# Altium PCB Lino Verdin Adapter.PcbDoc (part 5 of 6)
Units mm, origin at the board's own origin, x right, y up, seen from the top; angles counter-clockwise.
Board outline 69.6 x 35 mm, 8 copper layers (Top Layer, Mid 1, GND 1, Mid 2, Mid 3, GND 2, Mid 4, Bottom Layer), stack 1.198 mm thick; 208 components, 258 nets, 1063 pads, 1090 vias.
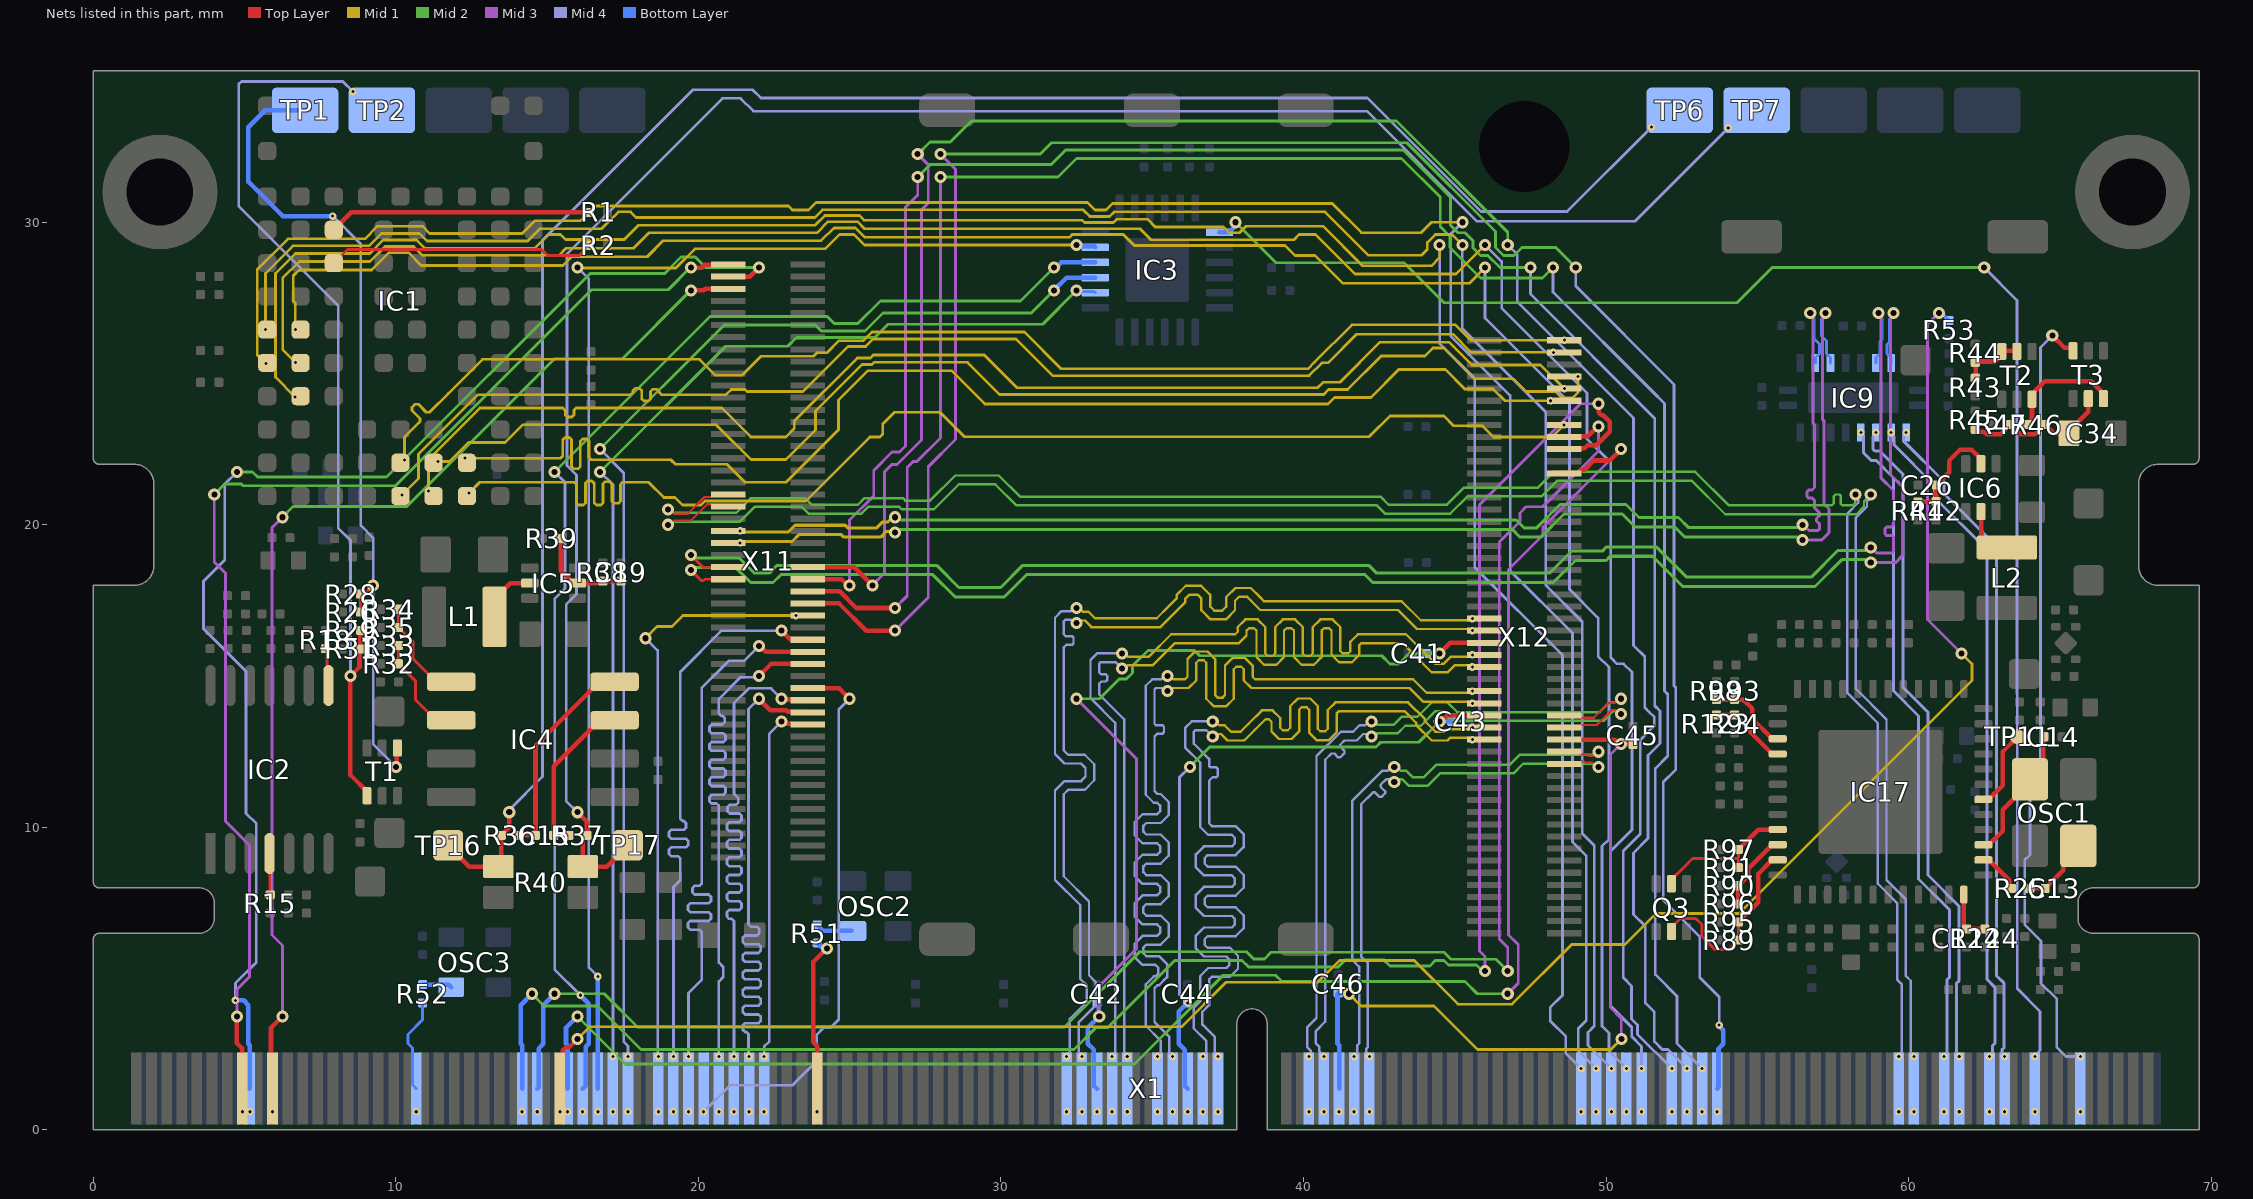
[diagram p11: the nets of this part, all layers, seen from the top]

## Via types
v1: diameter 0.4, hole 0.2, Top Layer to Bottom Layer, tented both sides, 600 vias
v2: diameter 0.25, hole 0.1, Mid 4 to Bottom Layer, tented both sides, 229 vias
v3: diameter 0.25, hole 0.1, Top Layer to Mid 1, tented both sides, 216 vias
v4: diameter 0.25, hole 0.1, Top Layer to Mid 1, tented top, 41 vias
v5: diameter 0.4, hole 0.2, Top Layer to Bottom Layer, 4 vias

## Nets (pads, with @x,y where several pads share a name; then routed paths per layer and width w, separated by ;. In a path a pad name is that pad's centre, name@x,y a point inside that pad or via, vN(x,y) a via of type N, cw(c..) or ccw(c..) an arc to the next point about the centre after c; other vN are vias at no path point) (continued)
MSP_16/17_N: X1.124 X12.S47 | length 32.8
  Mid 4 w0.08: v2(32.175,2.425) 32.175,2.452 32.28,2.557 32.28,3.671 32.84,4.231 32.84,4.769 32.62,4.989 32.62,7.43 31.787,8.263 31.787,9.34 31.787,11.215 32.102,11.53 32.651,11.53 32.796,11.675 32.796,11.965 32.651,12.11 32.102,12.11 31.787,12.425 31.787,12.67 31.787,16.928 32.004,17.145 32.308,17.145 32.413,17.25 v1(32.5,17.25)
  Mid 1 w0.08: v1(32.5,17.25) 32.587,17.25 32.711,17.126 32.893,17.126 33.109,16.91 35.15,16.91 35.55,17.31 35.807,17.568 35.807,17.682 36.11,17.984 36.615,17.984 36.917,17.682 36.917,17.298 37.05,17.165 37.315,17.165 37.447,17.298 37.447,17.607 37.75,17.91 38.255,17.91 38.557,17.607 38.69,17.475 40.195,17.475 43.245,17.475 43.875,16.845 45.479,16.845 45.534,16.9 v3(45.58,16.9)
  other v2: 32.175,0.6
MSP_16/17_P: X1.126 X12.S49 | length 32.8
  Mid 4 w0.08: v1(32.5,16.75) 32.413,16.75 32.308,16.855 32.124,16.855 32.077,16.808 32.077,16.383 32.14,16.32 32.353,16.32 32.4,16.273 32.4,16.077 32.353,16.03 32.157,16.03 32.077,15.95 32.077,12.67 32.077,12.545 32.222,12.4 32.771,12.4 33.086,12.085 33.086,11.555 32.771,11.24 32.222,11.24 32.077,11.095 32.077,9.34 32.077,8.383 32.91,7.55 32.91,5.109 33.13,4.889 33.13,4.111 32.57,3.551 32.57,2.557 32.675,2.452 v2(32.675,2.425)
  Mid 1 w0.08: v1(32.5,16.75) 32.587,16.75 32.673,16.836 32.773,16.836 32.989,16.62 35.27,16.62 35.55,16.9 36.097,17.447 36.097,17.562 36.23,17.694 36.495,17.694 36.627,17.562 36.627,17.178 36.93,16.875 37.435,16.875 37.737,17.178 37.737,17.487 37.87,17.62 38.135,17.62 38.267,17.487 38.57,17.185 40.195,17.185 40.44,17.185 43.125,17.185 43.755,16.555 45.479,16.555 45.534,16.5 v3(45.58,16.5)
  other v2: 32.675,0.6
MSP_18: C41.2 C42.2 X1.128 X12.S51 | length 30.2
  Top Layer w0.15: v1(44.5,15.75) 44.85,16.1 X12.S51@45.98,16.1
  Mid 3 w0.095: v1(32.5,14.25) 34.48,12.27 34.48,5.989 33.25,4.759 v1(33.25,3.75)
  Mid 2 w0.095: v1(32.5,14.25) 33.259,14.25 33.911,14.902 34.144,14.902 34.348,15.106 34.348,15.339 34.859,15.85 36.39,15.85 36.57,15.67 42.589,15.67 42.856,15.403 43.144,15.403 43.491,15.75 v1(44.5,15.75)
  Bottom Layer w0.15: C42.2@33.17,4.2 33.236,4.134 33.236,3.764 v1(33.25,3.75) 32.875,3.375 32.875,2.845 33.075,2.645 33.075,1.462 X1.128@33.175,1.362 ; C41.2@44.06,15.75 v1(44.5,15.75)
  other v2: 33.175,0.6
MSP_19/20_N: X1.130 X12.S53 | length 32.8
  Mid 4 w0.08: v2(33.675,2.425) 33.675,2.452 33.78,2.557 33.78,4.062 33.78,13.451 32.96,14.271 32.96,15.533 33.177,15.75 v1(34,15.75)
  Mid 1 w0.08: v1(34,15.75) 34.087,15.75 34.192,15.645 34.895,15.645 35.63,16.38 37.745,16.38 37.827,16.462 37.827,16.62 38.08,16.873 38.485,16.873 38.737,16.62 38.737,15.745 38.82,15.663 38.985,15.663 39.067,15.745 39.067,16.62 39.32,16.873 39.725,16.873 39.977,16.62 39.977,15.745 40.06,15.663 40.225,15.663 40.307,15.745 40.307,16.62 40.56,16.873 40.965,16.873 41.217,16.62 41.217,15.831 41.3,15.749 41.479,15.749 41.547,15.817 41.547,16.128 41.8,16.38 43.389,16.38 44.359,15.41 44.641,15.41 44.876,15.645 45.479,15.645 45.534,15.7 v3(45.58,15.7)
  other v2: 33.675,0.6
MSP_19/20_P: X1.132 X12.S55 | length 32.8
  Mid 4 w0.08: v1(34,15.25) 33.79,15.46 33.297,15.46 33.25,15.413 33.25,15.12 33.31,15.06 33.463,15.06 33.51,15.013 33.51,14.867 33.463,14.82 33.32,14.82 33.25,14.75 33.25,14.391 34.07,13.571 34.07,3.942 34.07,2.557 34.175,2.452 v2(34.175,2.425)
  Mid 1 w0.08: v1(34,15.25) 34.087,15.25 34.192,15.355 35.015,15.355 35.75,16.09 37.62,16.09 37.865,16.09 38.117,16.342 38.117,16.5 38.2,16.583 38.365,16.583 38.447,16.5 38.447,15.625 38.7,15.373 39.105,15.373 39.357,15.625 39.357,16.5 39.44,16.583 39.605,16.583 39.687,16.5 39.687,15.625 39.94,15.373 40.345,15.373 40.597,15.625 40.597,16.5 40.68,16.583 40.845,16.583 40.927,16.5 40.927,15.711 41.18,15.459 41.599,15.459 41.837,15.697 41.837,16.008 41.92,16.09 42.729,16.09 43.269,16.09 44.239,15.12 44.761,15.12 44.996,15.355 45.479,15.355 45.534,15.3 v3(45.58,15.3)
  other v2: 34.175,0.6
MSP_21/22_N: X1.136 X12.S59 | length 32.8
  Mid 4 w0.08: v2(35.175,2.425) 35.175,2.452 35.28,2.557 35.28,2.951 34.787,3.444 34.787,4.15 34.787,4.808 35.052,5.073 35.11,5.073 35.205,5.168 35.205,5.358 35.11,5.453 34.683,5.453 34.418,5.718 34.418,6.148 34.683,6.413 35.164,6.413 35.259,6.508 35.259,6.698 35.164,6.793 34.683,6.793 34.418,7.058 34.418,7.488 34.683,7.753 35.164,7.753 35.259,7.848 35.259,8.038 35.164,8.133 34.683,8.133 34.418,8.398 34.418,8.828 34.683,9.093 35.164,9.093 35.259,9.188 35.259,9.378 35.164,9.473 34.683,9.473 34.418,9.738 34.418,10.168 34.683,10.433 35.164,10.433 35.259,10.528 35.259,10.718 35.164,10.813 35.052,10.813 34.787,11.078 34.787,11.323 34.787,14.678 35.004,14.895 35.308,14.895 35.413,15 v1(35.5,15)
  Mid 1 w0.08: v1(35.5,15) 35.587,15 35.692,14.895 36.085,14.895 36.167,14.977 36.167,15.559 36.42,15.812 36.825,15.812 37.077,15.559 37.077,14.368 37.16,14.286 37.325,14.286 37.407,14.368 37.407,15.345 37.66,15.597 38.065,15.597 38.317,15.345 38.317,14.977 38.4,14.895 43.624,14.895 44.074,14.445 45.479,14.445 45.534,14.5 v3(45.58,14.5)
  other v2: 35.175,0.6
MSP_21/22_P: X1.138 X12.S61 | length 32.8
  Mid 4 w0.08: v1(35.5,14.5) 35.413,14.5 35.308,14.605 35.124,14.605 35.077,14.558 35.077,13.423 35.13,13.37 35.343,13.37 35.39,13.323 35.39,13.147 35.343,13.1 35.18,13.1 35.077,12.997 35.077,11.323 35.077,11.198 35.172,11.103 35.284,11.103 35.549,10.838 35.549,10.408 35.284,10.143 34.803,10.143 34.708,10.048 34.708,9.858 34.803,9.763 35.284,9.763 35.549,9.498 35.549,9.068 35.284,8.803 34.803,8.803 34.708,8.708 34.708,8.518 34.803,8.423 35.284,8.423 35.549,8.158 35.549,7.728 35.284,7.463 34.803,7.463 34.708,7.368 34.708,7.178 34.803,7.083 35.284,7.083 35.549,6.818 35.549,6.388 35.284,6.123 34.803,6.123 34.708,6.028 34.708,5.838 34.803,5.743 35.23,5.743 35.495,5.478 35.495,5.048 35.23,4.783 35.172,4.783 35.077,4.688 35.077,4.15 35.077,3.564 35.57,3.071 35.57,2.557 35.675,2.452 v2(35.675,2.425)
  Mid 1 w0.08: v1(35.5,14.5) 35.587,14.5 35.692,14.605 35.96,14.605 36.205,14.605 36.457,14.857 36.457,15.439 36.54,15.522 36.705,15.522 36.787,15.439 36.787,14.248 37.04,13.996 37.445,13.996 37.697,14.248 37.697,15.225 37.78,15.307 37.945,15.307 38.027,15.225 38.027,14.857 38.28,14.605 38.82,14.605 43.504,14.605 43.954,14.155 45.479,14.155 45.534,14.1 v3(45.58,14.1)
  other v2: 35.675,0.6
MSP_23: C43.2 C44.2 X1.140 X12.S63 | length 22
  Top Layer w0.15: v1(44.5,13.5) 44.568,13.5 44.768,13.7 X12.S63@45.98,13.7
  Mid 2 w0.095: v1(36.25,12) 36.902,12.652 42.394,12.652 42.554,12.812 43.812,12.812 v1(44.5,13.5)
  Mid 4 w0.09: v2(36.17,4.2) 35.905,4.465 35.905,11.655 v1(36.25,12)
  Bottom Layer w0.15: v2(36.17,4.2) 35.883,3.913 35.883,3.603 35.875,3.595 35.875,2.845 36.075,2.645 36.075,1.462 X1.140@36.175,1.362 ; v1(44.5,13.5) C43.2@44.9,13.5
  other v2: 36.175,0.6
MSP_24/25_N: X1.142 X12.S65 | length 32.8
  Mid 4 w0.08: v2(36.675,2.425) 36.675,2.452 36.78,2.557 36.78,2.951 36.37,3.361 36.37,4.025 36.59,4.245 36.59,4.67 36.59,4.72 36.59,4.84 36.59,5.085 36.855,5.35 37.451,5.35 37.546,5.445 37.546,5.635 37.451,5.73 36.71,5.73 36.445,5.995 36.445,6.425 36.71,6.69 37.635,6.69 37.73,6.785 37.73,6.975 37.635,7.07 36.71,7.07 36.445,7.335 36.445,7.765 36.71,8.03 37.635,8.03 37.73,8.125 37.73,8.315 37.635,8.41 36.71,8.41 36.445,8.675 36.445,9.105 36.71,9.37 37.635,9.37 37.73,9.465 37.73,9.655 37.635,9.75 36.855,9.75 36.59,10.015 36.59,10.26 36.59,12.141 36.09,12.641 36.09,13.283 36.307,13.5 v1(37,13.5)
  Mid 1 w0.08: v1(37,13.5) 37.087,13.5 37.211,13.376 37.393,13.376 37.609,13.16 37.92,13.16 38.15,13.39 38.19,13.43 38.625,13.865 38.982,13.865 39.234,13.612 39.234,13.292 39.316,13.21 39.481,13.21 39.564,13.292 39.564,14.005 39.816,14.258 40.222,14.258 40.474,14.005 40.474,13.257 40.556,13.175 40.721,13.175 40.804,13.257 40.804,13.878 41.056,14.13 41.301,14.13 43.46,14.13 44.012,13.578 44.012,13.507 44.359,13.16 44.641,13.16 44.726,13.245 45.479,13.245 45.534,13.3 v3(45.58,13.3)
  other v2: 36.675,0.6
MSP_24/25_P: X1.144 X12.S67 | length 32.8
  Mid 4 w0.08: v1(37,13) 36.79,13.21 36.427,13.21 36.38,13.163 36.38,12.761 36.88,12.261 36.88,12.03 36.93,11.98 37.123,11.98 37.17,11.933 37.17,11.707 37.123,11.66 37,11.66 36.88,11.54 36.88,10.26 36.88,10.135 36.975,10.04 37.755,10.04 38.02,9.775 38.02,9.345 37.755,9.08 36.83,9.08 36.735,8.985 36.735,8.795 36.83,8.7 37.755,8.7 38.02,8.435 38.02,8.005 37.755,7.74 36.83,7.74 36.735,7.645 36.735,7.455 36.83,7.36 37.755,7.36 38.02,7.095 38.02,6.665 37.755,6.4 36.83,6.4 36.735,6.305 36.735,6.115 36.83,6.02 37.571,6.02 37.836,5.755 37.836,5.325 37.571,5.06 36.975,5.06 36.88,4.965 36.88,4.84 36.88,4.125 36.66,3.905 36.66,3.481 37.07,3.071 37.07,2.557 37.175,2.452 v2(37.175,2.425)
  Mid 1 w0.08: v1(37,13) 37.087,13 37.173,13.086 37.273,13.086 37.489,12.87 38.04,12.87 38.15,12.98 38.395,13.225 38.745,13.575 38.861,13.575 38.944,13.492 38.944,13.172 39.196,12.92 39.602,12.92 39.854,13.172 39.854,13.885 39.936,13.968 40.101,13.968 40.184,13.885 40.184,13.137 40.436,12.885 40.842,12.885 41.094,13.137 41.094,13.758 41.176,13.84 43.34,13.84 43.722,13.458 43.722,13.387 44.239,12.87 44.761,12.87 44.846,12.955 45.479,12.955 45.534,12.9 v3(45.58,12.9)
  other v2: 37.175,0.6
MSP_26/27_N: X1.148 X12.S64 | length 23.5
  Top Layer w0.075: X12.S64@48.62,13.7 49.09,13.7 49.171,13.619 49.596,13.619 50.096,14.118 50.294,14.118 50.425,14.25 v1(50.5,14.25)
  Mid 2 w0.08: v1(42.25,13.5) 42.337,13.5 42.442,13.395 42.987,13.395 43.242,13.65 43.759,13.65 44.239,14.13 44.761,14.13 45.081,13.81 49.791,13.81 50.107,14.126 50.289,14.126 50.413,14.25 v1(50.5,14.25)
  Mid 4 w0.08: v2(40.175,2.425) 40.175,2.471 40.236,2.532 40.236,2.623 40.12,2.739 40.12,3.389 40.43,3.699 40.43,12.353 41.237,13.16 41.641,13.16 41.857,13.376 42.039,13.376 42.163,13.5 v1(42.25,13.5)
  other v2: 40.175,0.6
MSP_26/27_P: X1.150 X12.S66 | length 23.5
  Top Layer w0.075: X12.S66@48.62,13.3 49.09,13.3 49.171,13.381 49.694,13.381 50.194,13.881 50.294,13.881 50.425,13.75 v1(50.5,13.75)
  Mid 2 w0.08: v1(42.25,13) 42.337,13 42.442,13.105 43.108,13.105 43.363,13.36 43.879,13.36 44.359,13.84 44.641,13.84 44.961,13.52 49.911,13.52 50.227,13.836 50.327,13.836 50.413,13.75 v1(50.5,13.75)
  Mid 4 w0.08: v2(40.675,2.425) 40.675,2.452 40.526,2.601 40.526,2.743 40.41,2.859 40.41,3.269 40.72,3.579 40.72,12.233 40.927,12.44 41.02,12.44 41.147,12.313 41.213,12.313 41.357,12.457 41.357,12.523 41.217,12.663 41.217,12.73 41.357,12.87 41.761,12.87 41.977,13.086 42.077,13.086 42.163,13 v1(42.25,13)
  other v2: 40.675,0.6
MSP_28: C45.2 C46.2 X1.152 X12.S68 | length 25.8
  Top Layer w0.15: X12.S68@48.62,12.9 50.282,12.9 50.432,12.75 v1(50.5,12.75) 50.505,12.745 50.885,12.745 C45.2@50.89,12.74
  Mid 3 w0.095: v1(50.5,12.75) 50.153,12.402 50.153,4.042 50.505,3.689 v1(50.505,3.005)
  Mid 1 w0.09: v1(41.5,4.5) 41.905,4.095 44.315,4.095 45.755,2.655 50.155,2.655 v1(50.505,3.005)
  Bottom Layer w0.15: X1.152@41.175,1.362 41.175,2.795 41.125,2.845 41.125,3.155 41.125,4.505 C46.2@41.15,4.53 41.165,4.515 41.485,4.515 v1(41.5,4.5)
  other v2: 41.175,0.6
MSP_29/30_N: X1.154 X12.S70 | length 18.9
  Top Layer w0.075: X12.S70@48.62,12.5 49.09,12.5 49.174,12.416 49.357,12.416 49.404,12.369 49.544,12.369 49.675,12.5 v1(49.75,12.5)
  Mid 2 w0.08: v1(43,12) 43.087,12 43.211,11.876 43.393,11.876 43.609,11.66 43.98,11.66 44.395,12.075 46.825,12.075 47.145,12.395 49.558,12.395 49.663,12.5 v1(49.75,12.5)
  Mid 4 w0.08: v2(41.675,2.425) 41.675,2.452 41.78,2.557 41.78,2.799 41.84,2.859 41.84,5.391 41.615,5.616 41.615,10.884 42.607,11.876 42.789,11.876 42.913,12 v1(43,12)
  other v2: 41.675,0.6
MSP_29/30_P: X1.156 X12.S72 | length 18.9
  Top Layer w0.075: X12.S72@48.62,12.1 48.682,12.163 49.18,12.163 49.196,12.179 49.259,12.179 49.306,12.132 49.544,12.132 49.675,12 v1(49.75,12)
  Mid 2 w0.08: v1(43,11.5) 43.087,11.5 43.173,11.586 43.273,11.586 43.489,11.37 44.1,11.37 44.515,11.785 46.945,11.785 47.265,12.105 49.558,12.105 49.663,12 v1(49.75,12)
  Mid 4 w0.08: v2(42.175,2.425) 42.175,2.452 42.07,2.557 42.07,2.679 42.13,2.739 42.13,5.511 41.905,5.736 41.905,10.764 42.297,11.156 42.364,11.156 42.512,11.008 42.578,11.008 42.697,11.127 42.697,11.193 42.549,11.341 42.549,11.408 42.727,11.586 42.827,11.586 42.913,11.5 v1(43,11.5)
  other v2: 42.175,0.6
MSP_33/34_N: IC9.3 X11.P45 | length 46.4
  Mid 3 w0.1: v1(56.5,20) 56.519,20 56.709,19.81 57.001,19.81 57.06,19.869 57.06,20.03 57.05,20.03 56.956,20.124 56.956,20.206 57.059,20.309 57.059,20.392 56.89,20.562 56.89,20.81 56.82,20.88 56.699,20.88 56.64,20.939 56.64,21.091 56.699,21.15 56.81,21.15 56.89,21.23 56.89,23.314 56.845,23.359 56.845,26.824 56.75,26.919 v1(56.75,27)
  Mid 2 w0.1: v1(26.5,20.25) 26.581,20.25 26.676,20.155 36.404,20.155 36.409,20.16 47.028,20.16 47.288,19.9 47.712,19.9 48.482,20.67 50.66,20.67 51.09,20.24 52.398,20.24 52.733,19.905 56.324,19.905 56.419,20 v1(56.5,20)
  Mid 1 w0.1: v3(21.38,19.8) 21.409,19.771 21.497,19.771 21.514,19.755 22.964,19.755 23.194,19.985 24.852,19.985 24.937,19.9 25.895,19.9 26.08,20.085 26.254,20.085 26.419,20.25 v1(26.5,20.25)
  Bottom Layer w0.095: v1(56.75,27) 56.75,26.923 56.881,26.792 56.881,26.141 57.051,25.971 57.051,25.656 56.92,25.525 IC9.3@56.92,25.35
MSP_33/34_P: IC9.4 X11.P47 | length 46.4
  Mid 3 w0.1: v1(56.5,19.5) 57.13,19.5 57.37,19.74 57.37,20.52 57.2,20.69 57.2,23.442 57.155,23.487 57.155,26.824 57.25,26.919 v1(57.25,27)
  Mid 2 w0.1: v1(26.5,19.75) 26.581,19.75 26.676,19.845 36.533,19.845 36.538,19.85 46.9,19.85 47.16,19.59 47.84,19.59 48.61,20.36 50.532,20.36 50.962,19.93 52.27,19.93 52.605,19.595 56.324,19.595 56.419,19.5 v1(56.5,19.5)
  Mid 1 w0.1: v3(21.38,19.4) 21.409,19.429 21.497,19.429 21.514,19.445 23.092,19.445 23.322,19.675 24.724,19.675 24.809,19.59 26.023,19.59 26.209,19.775 26.475,19.775 v1(26.5,19.75)
  Bottom Layer w0.095: v1(57.25,27) 57.25,26.923 57.119,26.792 57.119,26.24 57.289,26.07 57.289,25.656 57.42,25.525 IC9.4@57.42,25.35
MSP_35/36_N: IC9.7 X11.P51 | length 53.8
  Top Layer w0.095: v1(19.75,19) 20.153,18.597 20.89,18.597 20.933,18.553 X11.P51@20.98,18.6
  Mid 3 w0.1: v1(58.75,19.25) 58.769,19.25 58.959,19.06 59.441,19.06 59.5,19.119 59.5,19.61 59.47,19.64 59.279,19.64 59.22,19.699 59.22,19.871 59.279,19.93 59.43,19.93 59.5,20 59.5,21.132 59.095,21.537 59.095,26.824 59,26.919 v1(59,27)
  Mid 2 w0.1: v1(19.75,19) 19.831,19 19.926,18.905 21.35,18.905 21.855,18.4 22.342,18.4 22.602,18.66 27.878,18.66 28.608,17.93 29.99,17.93 30.72,18.66 42.158,18.66 42.418,18.4 48.132,18.4 48.862,19.13 49.875,19.13 50.015,19.27 51.663,19.27 52.663,18.27 56.78,18.27 57.665,19.155 58.574,19.155 58.669,19.25 v1(58.75,19.25)
  Bottom Layer w0.095: IC9.7@58.92,25.35 58.92,25.525 59.051,25.656 59.051,26.06 59.131,26.14 59.131,26.792 59,26.923 v1(59,27)
MSP_35/36_P: IC9.8 X11.P53 | length 53.8
  Top Layer w0.095: v1(19.75,18.5) 20.096,18.154 20.174,18.154 20.22,18.2 X11.P53@20.98,18.2
  Mid 3 w0.1: v1(58.75,18.75) 59.57,18.75 59.81,18.99 59.81,21.26 59.405,21.665 59.405,26.824 59.5,26.919 v1(59.5,27)
  Mid 2 w0.1: v1(19.75,18.5) 19.831,18.5 19.926,18.595 21.222,18.595 21.727,18.09 22.47,18.09 22.73,18.35 27.75,18.35 28.48,17.62 30.118,17.62 30.848,18.35 42.03,18.35 42.29,18.09 48.26,18.09 48.99,18.82 50.003,18.82 50.143,18.96 51.535,18.96 52.535,17.96 56.908,17.96 57.793,18.845 58.574,18.845 58.669,18.75 v1(58.75,18.75)
  Bottom Layer w0.095: IC9.8@59.42,25.35 59.42,25.525 59.289,25.656 59.289,25.961 59.369,26.041 59.369,26.792 59.5,26.923 v1(59.5,27)
NetC13_2: C13.2 OSC1.1 R25.1 | length 2.4
  Top Layer w0.15: R25.1@64.006,7.98 C13.2@64.513,7.98 65.114,8.581 65.114,8.89 OSC1.1@65.611,9.387
NetC14_2: C14.2 IC17.15 OSC1.3 | length 4.5
  Top Layer w0.15: IC17.15@62.475,9.425 62.655,9.425 63.107,9.877 63.107,10.583 64.011,11.487 OSC1.3@64.011,11.587 64.448,12.024 64.448,12.963 C14.2@64.479,12.995
NetC15_1: C15.1 IC4.7 R37.2 | length 5.4
  Top Layer w0.15: R37.2@15.719,9.736 C15.1@15.216,9.736 15.216,12.016 16.505,13.305 16.505,13.309 16.738,13.542 IC4.7@17.23,13.542
NetC15_2: C15.2 IC4.8 R36.2 | length 7
  Top Layer w0.15: R36.2@14.087,9.736 C15.2@14.616,9.736 14.616,12.696 16.732,14.812 IC4.8@17.23,14.812
NetC19_1: C19.1 IC5.5 R38.1 R39.2 | length 3.3
  Top Layer w0.15: R39.2@15.447,19.553 15.447,18.479 15.679,18.248 15.696,18.248 15.871,18.073 IC5.5@16.006,18.073 16.627,18.073 16.692,18.138 R38.1@16.841,18.138 C19.1@17.441,18.138
NetC26_1: C26.1 IC6.5 R41.1 R42.2 | length 3.6
  Top Layer w0.15: R41.1@60.306,20.752 60.312,20.757 60.905,20.757 R42.2@60.91,20.763 60.913,20.766 60.913,21.31 C26.1@60.916,21.313 61.345,21.742 61.345,22.123 61.698,22.477 62.082,22.477 62.315,22.243 62.315,22.092 IC6.5@62.39,22.017
NetC34_2: C34.2 R45.1 R46.1 R47.2 T3.2 | length 5.1
  Top Layer w0.15: R45.1@62.204,23.152 62.279,23.077 62.487,23.077 62.576,22.988 63.045,22.988 R47.2@63.37,23.313 63.695,22.988 64.189,22.988 R46.1@64.514,23.313 64.804,23.023 C34.2@65.302,23.023 65.302,23.098 65.939,23.735 T3.2@65.939,24.171
NetC124_2: C124.2 IC17.12 R124.2 | length 1.8
  Top Layer w0.15: IC17.12@61.825,7.775 61.825,6.737 C124.2@61.92,6.642 R124.2@62.52,6.642
NetIC1_H7: IC1.H7 R2.1 | length 8.9
  Top Layer w0.1: IC1.H7@7.95,28.65 8.4,29.1 14.824,29.1 15.024,28.9 16.063,28.9 R2.1@16.4,29.237
NetIC1_J7: IC1.J7 R1.1 | length 8.7
  Top Layer w0.15: IC1.J7@7.95,29.75 8.525,30.325 R1.1@16.4,30.325
NetIC2_4: IC2.4 R15.1 | length 1.4
  Top Layer w0.1: IC2.4@5.825,9.137 5.838,9.124 5.838,7.783 R15.1@5.85,7.77
NetIC2_8: IC2.8 R18.1 | length 1.3
  Top Layer w0.1: R18.1@7.68,15.908 7.729,15.859 7.729,14.734 IC2.8@7.775,14.687
NetIC4_1: IC4.1 R34.1 R35.1 | length 3.4
  Top Layer w0.1: R34.1@10.089,17.208 R35.1@10.089,16.608 10.56,16.137 10.56,15.58 11.328,14.812 IC4.1@11.83,14.812
NetIC4_2: IC4.2 R32.1 R33.1 | length 3.5
  Top Layer w0.1: R33.1@10.089,16.008 R32.1@10.089,15.408 10.647,14.85 10.647,14.223 11.328,13.542 IC4.2@11.83,13.542
NetIC5_2: IC5.2 L1.1 | length 2
  Top Layer w0.15: L1.1@13.266,16.955 13.266,17.552 13.786,18.073 IC5.2@14.426,18.073
NetIC6_2: IC6.2 L2.1 | length 1.9
  Top Layer w0.15: IC6.2@62.39,20.437 62.398,20.429 62.398,19.573 62.722,19.249 L2.1@63.25,19.249
NetIC17_14: IC17.14 R25.2 | length 1.4
  Top Layer w0.15: IC17.14@62.475,8.925 62.655,8.925 63.331,8.249 63.331,8.055 R25.2@63.406,7.98
NetIC17_18: IC17.18 TP11.1 | length 2.6
  Top Layer w0.15: IC17.18@62.475,10.925 62.655,10.925 63.12,11.39 63.12,12.508 TP11.1@63.607,12.995
NetIC17_39: IC17.39 R93.1 R98.2 | length 2.8
  Top Layer w0.15: R98.2@53.65,14.22 54.54,14.22 54.84,13.92 54.84,13.58 55.495,12.925 IC17.39@55.675,12.925
NetIC17_40: IC17.40 R94.1 R123.2 | length 2.6
  Top Layer w0.15: R123.2@53.65,13.72 R94.1@54.25,13.72 54.77,13.2 54.77,13.15 55.495,12.425 IC17.40@55.675,12.425
NetIC17_45: IC17.45 Q3.5 R91.1 R97.2 | length 4.8
  Top Layer w0.1: Q3.5@52.16,8.135 52.16,8.27 52.59,8.7 52.86,8.97 54.375,8.97 ; R91.1@54.375,8.67 54.375,8.97 ; R97.2@54.375,9.27 54.375,8.97
  Top Layer w0.15: R97.2@54.375,9.27 55.03,9.925 IC17.45@55.675,9.925
NetIC17_46: IC17.46 R90.1 R96.2 | length 2.6
  Top Layer w0.15: R96.2@54.375,7.47 R90.1@54.375,8.07 54.7,8.395 54.7,8.63 55.495,9.425 IC17.46@55.675,9.425
NetIC17_47: IC17.47 Q3.2 R89.1 R95.2 | length 6.5
  Top Layer w0.1: Q3.2@52.16,6.555 52.16,6.69 52.46,6.99 52.97,6.99 53.17,6.79 53.17,6.392 53.592,5.97 54.075,5.97 R89.1@54.375,6.27 R95.2@54.375,6.811
  Top Layer w0.15: R95.2@54.375,6.87 55.03,7.525 55.03,8.46 55.495,8.925 IC17.47@55.675,8.925
NetOSC2_3: OSC2.3 R51.1 | length 1.2
  Bottom Layer w0.15: R51.1@23.93,6.777 24.132,6.575 OSC2.3@25.075,6.575
NetOSC3_3: OSC3.3 R52.1 | length 1
  Bottom Layer w0.15: R52.1@10.885,4.8 11.753,4.8 OSC3.3@11.835,4.718
NetR26_1: R26.1 R28.2 T1.1 TP1.1 | length 28
  Top Layer w0.1: R26.1@8.83,17.112 R28.2@8.83,17.712 8.906,17.787 9.037,17.787 v1(9.25,18)
  Top Layer w0.15: v1(10,12) 10.025,12.025 10.025,12.598 T1.1@10.05,12.623
  Mid 4 w0.09: v2(7.91,30.2) 7.918,30.2 8.845,29.273 8.845,19.975 9.25,19.57 v1(9.25,18) 9.25,12.75 v1(10,12)
  Bottom Layer w0.15: TP1.1@7,33.7 5.68,33.7 5.125,33.145 5.125,31.345 6.27,30.2 v2(7.91,30.2)
NetR29_1: R29.1 R31.2 T1.4 TP2.1 | length 30.9
  Top Layer w0.15: R29.1@8.83,16.512 R31.2@8.83,15.896 8.8,15.866 8.8,15.3 v1(8.5,15) 8.5,11.728 9.05,11.178 T1.4@9.05,11.043
  Mid 4 w0.09: v1(8.5,15) 8.5,19.49 8.095,19.895 8.095,27.243 4.805,30.533 4.805,34.56 4.9,34.655 8.245,34.655 v2(8.58,34.32)
NetR36_1: R36.1 R40.3 TP6.1 TP16.1 | length 64.8
  Top Layer w0.15: TP16.1@11.726,9.407 12.432,8.701 R40.3@13.391,8.701 13.487,8.797 R36.1@13.487,9.736 13.75,9.999 v1(13.75,10.5)
  Mid 4 w0.09: v1(13.75,10.5) 13.75,10.579 14.845,11.674 14.845,29.405 19.82,34.38 21.79,34.38 22.065,34.105 42.115,34.105 45.865,30.355 48.715,30.355 v2(51.5,33.14)
NetR37_1: R37.1 R40.2 TP7.1 TP17.1 | length 66.1
  Top Layer w0.15: v1(16,10.5) 16.319,10.181 R37.1@16.319,9.736 16.185,9.602 R40.2@16.185,8.701 16.966,8.701 TP17.1@17.672,9.407
  Mid 4 w0.09: v1(16,10.5) 15.63,10.87 15.63,17.368 15.97,17.708 15.97,21.64 15.655,21.955 15.655,28.955 20.795,34.095 21.393,34.095 21.818,33.67 42.1,33.67 45.74,30.03 50.95,30.03 v2(54.04,33.12)
NetR43_1: R43.1 R44.2 T2.2 T2.3 | length 2.1
  Top Layer w0.15: R43.1@62.214,24.882 62.214,25.397 62.863,25.397 63.089,25.623 63.089,25.758 T2.2@63.589,25.758
NetR46_2: R46.2 T2.6 T3.3 | length 3.9
  Top Layer w0.15: R46.2@63.914,23.313 64.079,23.479 T2.6@64.079,24.148 64.154,24.223 64.154,24.394 64.5,24.74 66.04,24.74 66.364,24.416 66.364,24.246 T3.3@66.439,24.171
NetR51_2: R51.2 X1.91 | length 5.3
  Top Layer w0.15: X1.91@23.925,1.362 23.925,2.765 23.8,2.89 23.8,5.55 v1(24.25,6)
  Bottom Layer w0.15: R51.2@23.93,6.177 24.059,6.048 24.202,6.048 v1(24.25,6)
  other v3: 23.925,0.6
NetR52_2: R52.2 X1.38 | length 3.2
  Bottom Layer w0.1: X1.38@10.675,1.362 10.55,1.487 10.55,2.705 10.4,2.855 10.4,3.155 10.885,3.64 R52.2@10.885,4.2
  other v2: 10.675,0.6
NetR53_1: R53.1 X1.57 | length 67.5
  Top Layer w0.15: X1.57@15.425,1.362 15.525,1.462 15.525,2.637 15.613,2.725 15.725,2.725 v1(16,3)
  Mid 3 w0.095: v1(61,27) 60.63,26.63 60.63,16.87 v1(61.75,15.75)
  Mid 1 w0.09: v1(16,3) 16.405,3.405 35.965,3.405 37.44,4.88 40.47,4.88 41.19,5.6 43.662,5.6 45.107,4.155 46.893,4.155 48.868,6.13 50.626,6.13 51.651,7.155 54.395,7.155 62.095,14.855 62.095,15.405 v1(61.75,15.75)
  Bottom Layer w0.1: v1(61,27) 61.057,26.943 61.147,26.943 R53.1@61.34,26.75
  other v3: 15.425,0.6
NetT3_6: T3.6 X1.250 | length 26.2
  Top Layer w0.15: v1(64.75,26.25) 65.152,25.848 65.364,25.848 65.439,25.773 T3.6@65.439,25.751
  Mid 4 w0.09: v1(64.75,26.25) 64.36,25.86 64.36,11.29 64.01,10.94 64.01,9.09 63.835,8.915 63.835,6.785 64.38,6.24 64.38,4.84 64.9,4.32 64.9,2.73 65.205,2.425 v2(65.675,2.425)
  other v2: 65.675,0.6
PCIE_1_CLK_N: X1.226 X11.P39 | length 64.1
  Top Layer w0.075: v1(19,20.5) 19.075,20.5 19.206,20.369 19.649,20.369 20.199,20.919 20.429,20.919 20.51,21 X11.P39@20.98,21
  Mid 2 w0.08: v1(19,20.5) 19.087,20.5 19.192,20.395 21.254,20.395 21.739,20.88 23.539,20.88 23.759,20.66 25.269,20.66 25.489,20.88 26.761,20.88 26.841,20.8 27.659,20.8 28.489,21.63 29.93,21.63 30.63,20.93 42.55,20.93 42.82,20.66 44.73,20.66 45.3,21.23 47.75,21.23 48.27,21.75 52.95,21.75 54.06,20.64 57.46,20.64 57.53,20.71 57.53,20.943 57.587,21 57.713,21 57.76,20.953 57.76,20.687 57.807,20.64 58.148,20.64 58.235,20.727 58.235,20.985 v1(58.25,21)
  Mid 4 w0.08: v1(58.25,21) 58.25,20.913 58.336,20.827 58.336,20.727 57.97,20.361 57.97,14.46 58.98,13.45 58.98,8.14 59.62,7.5 59.62,4.968 59.78,4.808 59.78,2.557 59.675,2.452 v2(59.675,2.425)
  other v2: 59.675,0.6
PCIE_1_CLK_P: X1.228 X11.P41 | length 64.1
  Top Layer w0.075: v1(19,20) 19.075,20 19.206,20.131 19.747,20.131 20.297,20.682 20.428,20.682 20.51,20.6 X11.P41@20.98,20.6
  Mid 2 w0.08: v1(19,20) 19.087,20 19.192,20.105 21.374,20.105 21.859,20.59 23.419,20.59 23.639,20.37 25.389,20.37 25.609,20.59 26.641,20.59 26.721,20.51 27.779,20.51 28.609,21.34 29.81,21.34 30.51,20.64 42.43,20.64 42.7,20.37 44.85,20.37 45.42,20.94 47.87,20.94 48.39,21.46 52.83,21.46 53.94,20.35 58.269,20.35 58.525,20.607 58.525,20.772 58.75,20.997 v1(58.75,21)
  Mid 4 w0.08: v1(58.75,21) 58.75,20.913 58.626,20.789 58.626,20.607 58.26,20.241 58.26,14.58 59.27,13.57 59.27,8.26 59.91,7.62 59.91,5.088 60.07,4.928 60.07,2.557 60.175,2.452 v2(60.175,2.425)
  other v2: 60.175,0.6
PCIE_1_L0_RX_N: IC9.15 X1.232 | length 22
  Mid 4 w0.1: v2(58.42,23.05) 58.42,23.011 58.515,22.916 58.515,22.37 58.755,22.13 58.92,22.13 59.5,21.55 59.5,14.51 60.33,13.68 60.33,8.295 61.35,7.275 61.35,5.045 61.27,4.965 61.27,2.559 61.175,2.464 v2(61.175,2.425)
  other v2: 61.175,0.6
PCIE_1_L0_RX_P: IC9.14 X1.234 | length 22
  Mid 4 w0.1: v2(58.92,23.05) 58.92,23.011 58.825,22.916 58.825,22.499 58.884,22.44 59.048,22.44 59.81,21.678 59.81,14.638 60.64,13.808 60.64,8.423 61.66,7.403 61.66,4.917 61.58,4.837 61.58,2.559 61.675,2.464 v2(61.675,2.425)
  other v2: 61.675,0.6
PCIE_1_L0_TX_N: IC9.13 X1.238 | length 22.1
  Mid 4 w0.1: v2(59.42,23.05) 59.42,23.011 59.515,22.916 59.515,22.645 60.86,21.3 60.86,20.902 62.59,19.172 62.59,4.977 62.85,4.717 62.85,2.855 62.77,2.775 62.77,2.559 62.675,2.464 v2(62.675,2.425)
  other v2: 62.675,0.6
PCIE_1_L0_TX_P: IC9.12 X1.240 | length 22.1
  Mid 4 w0.1: v2(59.92,23.05) 59.92,23.011 59.825,22.916 59.825,22.773 61.17,21.428 61.17,21.03 62.9,19.3 62.9,5.105 63.16,4.845 63.16,2.727 63.08,2.647 63.08,2.559 63.175,2.464 v2(63.175,2.425)
  other v2: 63.175,0.6
PCIE_1_RESET#: IC3.1 X1.244 | length 54
  Mid 2 w0.095: v1(37.75,30) 39.09,28.66 43.32,28.66 44.64,27.34 54.331,27.34 55.491,28.5 v1(62.5,28.5)
  Mid 4 w0.09: v1(62.5,28.5) 63.58,27.42 63.58,14.408 63.595,14.393 63.595,4.665 64.345,3.915 64.345,2.623 64.175,2.453 v2(64.175,2.425)
  Bottom Layer w0.15: IC3.1@37.22,29.672 37.545,29.672 37.702,29.829 37.702,29.952 v1(37.75,30)
  other v2: 64.175,0.6
PCM_CLK: IC1.D8 X1.184 | length 75
  Mid 4 w0.09: v1(44.5,29.25) 44.5,25.988 45.66,24.828 45.66,18.59 48.56,15.69 48.56,4.45 48.155,4.045 48.155,3.607 48.67,3.092 48.67,2.53 v2(49.175,2.025)
  Mid 1 w0.09: v4(6.67,24.23) 6.02,24.88 6.02,28.31 6.68,28.97 9.14,28.97 9.58,29.41 10.69,29.41 10.97,29.13 14.58,29.13 15.045,29.595 15.445,29.595 15.61,29.43 17.55,29.43 18.02,29.9 23.86,29.9 24.18,30.22 25.324,30.22 25.474,30.07 32.68,30.07 32.76,29.99 33.72,29.99 33.83,30.1 34.84,30.1 35.1,29.84 37.35,29.84 37.535,29.655 37.893,29.655 38.108,29.87 40.65,29.87 41.96,28.56 44.23,28.56 44.5,28.83 v1(44.5,29.25)
  other v2: 49.175,0.6
PCM_DIN: IC1.E9 X1.186 | length 75.4
  Mid 4 w0.09: v1(45.25,30) 44.87,29.62 44.87,26.23 46.83,24.27 46.83,18.48 48.89,16.42 48.89,9.52 49.345,9.065 49.345,3.607 49.08,3.342 49.08,2.62 v2(49.675,2.025)
  Mid 1 w0.09: v4(5.71,25.33) 5.42,25.62 5.42,28.44 6.43,29.45 8.98,29.45 9.4,29.87 10.88,29.87 11.12,29.63 14.18,29.63 14.6,30.05 16.1,30.05 16.585,30.535 22.975,30.535 23.105,30.405 23.643,30.405 23.888,30.65 32.862,30.65 33.107,30.405 33.475,30.405 33.69,30.62 40.95,30.62 41.915,29.655 43.893,29.655 44.238,30 v1(45.25,30)
  other v2: 49.675,0.6
PCM_DOUT: IC1.F9 X1.188 | length 73.4
  Mid 4 w0.09: v1(45.25,29.25) 45.25,26.48 48.01,23.72 48.01,18 49.215,16.795 49.215,9.797 49.61,9.402 49.61,3.43 49.405,3.225 49.405,2.795 v2(50.175,2.025)
  Mid 1 w0.09: v4(5.69,26.46) 5.69,28.31 6.6,29.22 9.11,29.22 9.52,29.63 10.78,29.63 11.03,29.38 14.36,29.38 14.765,29.785 16.797,29.785 17.357,30.345 17.755,30.345 17.94,30.16 23.851,30.16 24.101,30.41 32.72,30.41 32.94,30.19 33.59,30.19 33.745,30.345 40.715,30.345 42.155,28.905 43.775,28.905 43.893,28.905 44.095,29.107 44.095,29.333 44.357,29.595 44.905,29.595 v1(45.25,29.25)
  other v2: 50.175,0.6
PCM_MCLK: IC1.E8 X1.192 | length 75.1
  Mid 4 w0.09: v1(46,29.25) 46.55,28.7 46.55,27.17 49.37,24.35 49.37,22.84 50.155,22.055 50.155,15.607 50.357,15.405 50.583,15.405 50.86,15.128 50.86,9.92 50.14,9.2 50.14,4.103 50.85,3.393 50.85,3.081 51.175,2.756 v2(51.175,2.025)
  Mid 1 w0.09: v4(6.68,25.37) 6.26,25.79 6.26,28.151 6.809,28.7 9.15,28.7 9.65,29.2 10.59,29.2 10.885,28.905 15.393,28.905 15.628,29.14 17.85,29.14 18.36,29.65 23.92,29.65 24.29,30.02 25.255,30.02 25.49,29.785 34.595,29.785 34.96,29.42 39.682,29.42 39.857,29.595 40.395,29.595 41.7,28.29 45.04,28.29 v1(46,29.25)
  other v2: 51.175,0.6
PCM_SYNC: IC1.F8 X1.190 | length 71.9
  Mid 4 w0.09: v1(46,28.5) 46,26.83 48.79,24.04 48.79,17.87 49.74,16.92 49.74,15.65 50.095,15.295 50.095,9.605 49.87,9.38 49.87,3.43 50.095,3.205 50.095,2.605 v2(50.675,2.025)
  Mid 1 w0.09: v4(6.69,26.45) 6.68,26.46 6.68,27.333 6.61,27.403 6.61,28.232 6.798,28.42 9.201,28.42 9.776,28.995 10.415,28.995 10.841,28.569 15.519,28.569 15.81,28.86 18.31,28.86 18.84,29.39 24.06,29.39 24.48,29.81 25.197,29.81 25.507,29.5 32.262,29.5 32.357,29.595 34.043,29.595 34.408,29.23 39.39,29.23 39.72,28.9 40.38,28.9 41.3,27.98 45.48,27.98 v1(46,28.5)
  other v2: 50.675,0.6
PWM_1: X1.15 X11.P1 | length 40.5
  Top Layer w0.15: v1(4.75,3.75) 4.75,2.866 4.925,2.691 X1.15@4.925,1.362 ; v1(19.75,28.5) 20.11,28.5 20.21,28.6 X11.P1@20.98,28.6
  Mid 3 w0.095: v1(4,21) 4,18.767 4.37,18.397 4.37,10.2 5.17,9.4 5.17,5.07 4.75,4.65 v1(4.75,3.75)
  Mid 2 w0.095: v1(4,21) 4.348,21.348 4.894,21.348 4.951,21.29 9.99,21.29 16.47,27.77 19.003,27.77 19.733,28.5 v1(19.75,28.5)
  other v3: 4.925,0.6
PWM_2: X1.16 X11.P3 | length 43.8
  Top Layer w0.15: X11.P3@20.98,28.2 21.7,28.2 v1(22,28.5)
  Mid 2 w0.095: v1(4.75,21.75) 5.266,21.75 5.436,21.58 9.694,21.58 16.414,28.3 18.88,28.3 19.427,28.847 19.894,28.847 20.241,28.5 v1(22,28.5)
  Mid 4 w0.09: v2(4.7,4.28) 4.7,4.85 5.39,5.54 5.39,10.122 5.05,10.462 5.05,15.16 3.645,16.565 3.645,18.133 4.345,18.833 4.345,21.345 v1(4.75,21.75)
  Bottom Layer w0.15: v2(4.7,4.28) 4.97,4.28 5.125,4.125 5.125,2.845 5.175,2.795 X1.16@5.175,1.362
  other v2: 5.175,0.6
PWM_3: X1.19 X11.P5 | length 37.2
  Top Layer w0.15: X1.19@5.925,1.362 5.875,1.412 5.875,3.375 v1(6.25,3.75) ; v1(19.75,27.75) 20.175,27.75 20.225,27.8 X11.P5@20.98,27.8
  Mid 3 w0.095: v1(6.25,3.75) 6.25,6.09 5.902,6.438 5.902,19.902 v1(6.25,20.25)
  Mid 2 w0.095: v1(6.25,20.25) 6.6,20.6 10.36,20.6 15.248,25.488 17.488,25.488 v1(19.75,27.75)
  other v3: 5.925,0.6
QSPI_1_CS2#: IC3.14 X1.64 | length 38.4
  Mid 2 w0.095: v1(16.75,21.75) 20.903,25.902 22.953,25.902 23.24,26.19 25.83,26.19 26.27,26.63 31.38,26.63 v1(32.5,27.75)
  Mid 4 w0.09: v1(16.75,21.75) 17.175,21.325 v2(17.175,2.425)
  Bottom Layer w0.1: v1(32.5,27.75) 32.539,27.711 33.081,27.711 IC3.14@33.12,27.672
  other v2: 17.175,0.6
QSPI_1_DQS: IC3.15 X1.66 | length 39.3
  Mid 2 w0.095: v1(16.75,22.5) 20.847,26.597 23.873,26.597 24.06,26.41 25.51,26.41 26.1,27 31,27 v1(31.75,27.75)
  Mid 4 w0.09: v1(16.75,22.5) 17.53,21.72 17.53,2.92 17.675,2.775 v2(17.675,2.425)
  Bottom Layer w0.15: v1(31.75,27.75) 32.172,28.172 IC3.15@33.12,28.172
  other v2: 17.675,0.6
QSPI_1_IO2: IC3.16 X1.60 | length 42.1
  Mid 2 w0.095: v1(15.25,21.75) 20.38,26.88 24.26,26.88 24.49,26.65 25.27,26.65 26.02,27.4 30.65,27.4 v1(31.75,28.5)
  Mid 4 w0.09: v1(15.25,21.75) 15.595,21.405 15.595,17.895 15.25,17.55 15.25,5.3 v2(16.1,4.45)
  Bottom Layer w0.15: v2(16.1,4.45) 16.375,4.175 16.375,2.845 16.275,2.745 16.275,1.462 X1.60@16.175,1.362 ; v1(31.75,28.5) 31.818,28.5 31.989,28.672 IC3.16@33.12,28.672
  other v2: 16.175,0.6
QSPI_1_IO3: IC3.17 X1.62 | length 45.2
  Mid 4 w0.09: v1(16,28.5) 16.38,28.12 16.38,5.37 v2(16.68,5.07)
  Mid 1 w0.09: v1(16,28.5) 16.01,28.49 19.252,28.49 19.882,29.12 24.19,29.12 24.665,29.595 25.143,29.595 25.488,29.25 v1(32.5,29.25)
  Bottom Layer w0.15: X1.62@16.675,1.362 16.678,1.365 16.678,5.068 v2(16.68,5.07) ; v1(32.5,29.25) 32.539,29.211 33.081,29.211 IC3.17@33.12,29.172
  other v2: 16.675,0.6
SD_1_CD#: X1.84 X11.P78 | length 12.2
  Top Layer w0.15: v1(22.75,13.5) 22.818,13.5 22.893,13.425 23.595,13.425 X11.P78@23.62,13.4
  Mid 4 w0.09: v2(22.175,2.425) 22.175,2.755 22.345,2.925 22.345,13.095 v1(22.75,13.5)
  other v2: 22.175,0.6
SD_1_CLK: X1.78 X11.P68 | length 19.7
  Top Layer w0.15: v1(22,15) 22.4,15.4 X11.P68@23.62,15.4
  Mid 4 w0.09: v2(20.675,2.425) 20.675,4.905 20.823,5.053 20.823,5.384 20.675,5.532 20.675,10.67 20.675,10.715 20.602,10.788 20.439,10.788 20.367,10.86 20.367,11.005 20.439,11.078 20.824,11.078 20.897,11.15 20.897,11.295 20.824,11.368 20.439,11.368 20.367,11.44 20.367,11.585 20.439,11.658 20.824,11.658 20.897,11.73 20.897,11.875 20.824,11.948 20.439,11.948 20.367,12.02 20.367,12.165 20.439,12.238 20.824,12.238 20.897,12.31 20.897,12.455 20.824,12.528 20.439,12.528 20.367,12.6 20.367,12.745 20.439,12.818 20.824,12.818 20.897,12.89 20.897,13.035 20.824,13.108 20.439,13.108 20.367,13.18 20.367,13.325 20.439,13.398 20.796,13.398 20.868,13.47 20.868,13.615 20.796,13.688 20.747,13.688 20.675,13.76 20.675,14.06 20.675,14.245 21.39,14.96 21.96,14.96 v1(22,15)
  other v2: 20.675,0.6
SD_1_CMD: X1.74 X11.P66 | length 19.7
  Top Layer w0.15: v1(22,16) 22.03,16 22.23,15.8 X11.P66@23.62,15.8
  Mid 4 w0.09: v2(19.675,2.425) 19.675,4.525 20.11,4.96 20.11,6.5 20.11,6.545 20.038,6.618 19.728,6.618 19.655,6.69 19.655,6.835 19.728,6.908 20.342,6.908 20.414,6.98 20.414,7.125 20.342,7.198 19.728,7.198 19.655,7.27 19.655,7.415 19.728,7.488 20.342,7.488 20.414,7.56 20.414,7.705 20.342,7.778 19.875,7.778 19.802,7.85 19.802,7.995 19.875,8.068 20.038,8.068 20.11,8.14 20.11,10.25 20.11,14.61 21.005,15.505 21.505,15.505 v1(22,16)
  other v2: 19.675,0.6
SD_1_D0: X1.80 X11.P74 | length 19.7
  Top Layer w0.15: v1(22.75,14.25) 22.775,14.225 23.595,14.225 X11.P74@23.62,14.2
  Mid 4 w0.09: v2(21.175,2.425) 21.175,6.86 21.175,6.905 21.103,6.978 21.017,6.978 20.945,7.05 20.945,7.195 21.017,7.268 21.352,7.268 21.425,7.34 21.425,7.485 21.352,7.558 21.017,7.558 20.945,7.63 20.945,7.775 21.017,7.848 21.352,7.848 21.425,7.92 21.425,8.065 21.352,8.138 21.017,8.138 20.945,8.21 20.945,8.355 21.017,8.428 21.352,8.428 21.425,8.5 21.425,8.645 21.352,8.718 21.017,8.718 20.945,8.79 20.945,8.935 21.017,9.008 21.352,9.008 21.425,9.08 21.425,9.225 21.352,9.298 21.017,9.298 20.945,9.37 20.945,9.515 21.017,9.588 21.352,9.588 21.425,9.66 21.425,9.805 21.352,9.878 21.017,9.878 20.945,9.95 20.945,10.095 21.017,10.168 21.352,10.168 21.425,10.24 21.425,10.385 21.352,10.458 21.039,10.458 20.966,10.53 20.966,10.675 21.039,10.748 21.248,10.748 21.32,10.82 21.32,10.965 21.248,11.038 21.175,11.11 21.175,12.38 21.175,14.105 21.665,14.595 22.405,14.595 v1(22.75,14.25)
  other v2: 21.175,0.6
SD_1_D1: X1.82 X11.P76 | length 19.7
  Top Layer w0.15: v1(22,14.25) 22.375,13.875 22.905,13.875 22.955,13.825 23.595,13.825 X11.P76@23.62,13.8
  Mid 4 w0.09: v2(21.675,2.425) 21.655,2.445 21.655,3.12 21.655,3.165 21.583,3.238 21.54,3.238 21.467,3.31 21.467,3.455 21.54,3.528 21.987,3.528 22.059,3.6 22.059,3.745 21.987,3.818 21.54,3.818 21.467,3.89 21.467,4.035 21.54,4.108 21.987,4.108 22.059,4.18 22.059,4.325 21.987,4.398 21.54,4.398 21.467,4.47 21.467,4.615 21.54,4.688 21.987,4.688 22.059,4.76 22.059,4.905 21.987,4.978 21.54,4.978 21.467,5.05 21.467,5.195 21.54,5.268 21.987,5.268 22.059,5.34 22.059,5.485 21.987,5.558 21.54,5.558 21.467,5.63 21.467,5.775 21.54,5.848 21.987,5.848 22.059,5.92 22.059,6.065 21.987,6.138 21.54,6.138 21.467,6.21 21.467,6.355 21.54,6.428 21.936,6.428 22.008,6.5 22.008,6.645 21.936,6.718 21.728,6.718 21.655,6.79 21.655,9.18 21.655,13.905 v1(22,14.25)
  other v2: 21.675,0.6
SD_1_D2: X1.70 X11.P60 | length 19.3
  Mid 4 w0.09: v1(18.25,16.25) 18.655,15.845 18.655,2.445 v2(18.675,2.425)
  Mid 1 w0.09: v1(18.25,16.25) 18.639,16.639 19.127,16.639 19.488,17 v3(23.22,17)
  other v2: 18.675,0.6
SD_1_D3: X1.72 X11.P64 | length 19.7
  Top Layer w0.15: v1(22.75,16.5) 23.025,16.225 23.595,16.225 X11.P64@23.62,16.2
  Mid 4 w0.09: v2(19.175,2.425) 19.175,8.035 19.405,8.265 19.405,8.93 19.405,8.975 19.333,9.048 19.102,9.048 19.029,9.12 19.029,9.265 19.102,9.338 19.59,9.338 19.663,9.41 19.663,9.555 19.59,9.628 19.102,9.628 19.029,9.7 19.029,9.845 19.102,9.918 19.521,9.918 19.593,9.99 19.593,10.135 19.521,10.208 19.477,10.208 19.405,10.28 19.405,11.49 19.405,15.143 20.762,16.5 v1(22.75,16.5)
  other v2: 19.175,0.6
SD_1_PWR_EN: X1.76 X11.P72 | length 18.5
  Top Layer w0.15: X11.P72@23.62,14.6 24.65,14.6 v1(25,14.25)
  Mid 4 w0.09: v2(20.175,0.6) 21.047,1.472 23.104,1.472 23.945,2.313 23.945,2.708 23.905,2.748 23.905,3.143 24.137,3.375 24.363,3.375 24.64,3.652 24.64,13.89 v1(25,14.25)
SD_2_CLK: IC1.A4 X12.S10 | length 43.1
  Mid 1 w0.09: v4(11.08,21.11) 11.08,22.162 12.777,23.859 15.19,23.859 15.525,23.859 15.598,23.786 15.598,23.637 15.67,23.564 15.815,23.564 15.888,23.637 15.888,23.786 15.96,23.859 19.09,23.859 20.781,23.859 21.735,22.905 22.893,22.905 23.17,23.182 23.17,23.43 25.255,25.515 25.686,25.515 25.781,25.61 29.45,25.61 30.53,24.53 40.47,24.53 40.65,24.71 41.198,24.71 42.523,26.035 44.815,26.035 45.565,25.285 47.835,25.285 v4(48.62,24.5)
SD_2_CMD: IC1.B4 X12.S8 | length 42.7
  Mid 1 w0.09: v4(11.39,22.09) 11.77,22.09 12.4,22.72 13.61,22.72 14.193,23.303 20.59,23.303 21.738,22.155 22.893,22.155 23.87,23.132 23.87,23.76 25.41,25.3 25.74,25.3 25.81,25.37 28.9,25.37 29.96,24.31 40.67,24.31 40.83,24.47 41.46,24.47 42.57,25.58 44.01,25.58 44.275,25.845 44.643,25.845 45.658,24.83 46.932,24.83 47.357,24.405 48.333,24.405 48.548,24.19 48.89,24.19 49.07,24.37 v4(49.07,24.9)
SD_2_D0: IC1.B3 X12.S12 | length 42.7
  Mid 1 w0.09: v4(12.28,22.2) 15.4,22.2 15.445,22.2 15.518,22.272 15.518,22.81 15.59,22.882 15.735,22.882 15.808,22.81 15.808,21.923 15.88,21.851 16.025,21.851 16.098,21.923 16.098,22.763 16.17,22.836 16.315,22.836 16.388,22.763 16.388,22.222 16.46,22.15 18.9,22.15 19.088,22.15 19.238,22 20.95,22 21.545,21.405 22.893,21.405 24.63,23.142 24.63,24.118 25.607,25.095 28.365,25.095 29.47,23.99 40.81,23.99 41.03,24.21 42.23,24.21 43.15,25.13 44.69,25.13 45.33,24.49 46.27,24.49 46.66,24.1 v4(48.17,24.1)
SD_2_D1: IC1.A3 X12.S16 | length 43.2
  Top Layer w0.15: v4(48.61,23.3) X12.S16@48.62,23.3
  Mid 1 w0.09: v4(12.42,21.05) 12.775,21.405 15.57,21.405 15.905,21.405 15.978,21.333 15.978,20.726 16.05,20.653 16.195,20.653 16.268,20.726 16.268,21.372 16.34,21.444 16.485,21.444 16.558,21.372 16.558,20.726 16.63,20.653 16.775,20.653 16.848,20.726 16.848,21.354 16.92,21.427 17.065,21.427 17.138,21.354 17.138,20.786 17.21,20.713 17.355,20.713 17.428,20.786 17.428,21.333 17.5,21.405 18.14,21.405 18.357,21.405 18.857,20.905 19.225,20.905 19.475,20.655 20.085,20.655 20.22,20.79 23.552,20.79 25.667,22.905 25.997,22.905 26.095,23.003 26.095,23.333 26.482,23.72 27.98,23.72 28.79,22.91 42.172,22.91 42.857,23.595 44.643,23.595 44.967,23.271 45.92,23.271 46.286,22.905 48.215,22.905 v4(48.61,23.3)
SD_2_D2: IC1.B5 X12.S2 | length 43.1
  Mid 1 w0.09: v4(10.29,22.14) 10.29,22.9 10.77,23.38 10.802,23.412 10.802,23.514 10.538,23.778 10.538,23.881 10.641,23.983 10.743,23.983 11.007,23.719 11.109,23.719 11.735,24.345 12.859,25.469 20.041,25.469 20.57,24.94 21.433,24.94 22.063,25.57 23.808,25.57 23.928,25.69 24.26,25.69 24.655,26.085 25.45,26.085 25.735,26.37 30.78,26.37 31.995,25.155 40.143,25.155 40.37,25.382 41.598,26.61 45.02,26.61 45.53,26.1 v4(48.62,26.1)
SD_2_D3: IC1.A5 X12.S4 | length 42.9
  Mid 1 w0.09: v4(10.2,20.98) 10.75,21.53 10.75,22.34 12.71,24.3 17.72,24.3 17.765,24.3 17.838,24.372 17.838,24.437 17.91,24.509 18.055,24.509 18.128,24.437 18.128,24.162 18.2,24.089 18.345,24.089 18.418,24.162 18.418,24.404 18.49,24.477 18.635,24.477 18.708,24.404 18.708,24.372 18.78,24.3 19.9,24.3 20.92,24.3 21.09,24.47 21.542,24.47 21.607,24.405 23.455,24.405 24.945,25.895 25.529,25.895 25.774,26.14 30.5,26.14 31.71,24.93 40.187,24.93 40.608,25.352 40.812,25.352 41.76,26.3 44.94,26.3 45.54,25.7 v4(48.26,25.7)
SPI_1_CLK: X1.196 X11.P52 | length 69.9
  Top Layer w0.15: X11.P52@23.62,18.6 25.15,18.6 v1(25.75,18)
  Mid 3 w0.095: v1(25.75,18) 26.153,18.402 26.153,21.752 26.39,21.99 26.57,21.99 27.38,22.8 27.38,30.413 27.598,30.631 27.598,31.903 v1(27.25,32.25)
  Mid 2 w0.095: v1(27.25,32.25) 27.653,32.653 28.323,32.653 29.018,33.347 43.072,33.347 46.75,29.67 v1(46.75,29.25)
  Mid 4 w0.09: v1(46.75,29.25) 47.07,28.93 47.07,27.36 50.905,23.525 50.905,16.015 51.28,15.64 51.28,13.958 51.42,13.818 51.595,13.643 51.595,13.357 51.42,13.182 51.13,12.892 51.13,9.78 50.57,9.22 50.57,5.03 50.845,4.755 50.845,3.667 51.04,3.472 51.04,3.16 v2(52.175,2.025)
  other v2: 52.175,0.6
SPI_1_CS: X1.202 X11.P58 | length 73
  Top Layer w0.15: X11.P58@23.62,17.4 24.65,17.4 25.55,16.5 v1(26.5,16.5)
  Mid 3 w0.095: v1(26.5,16.5) 27.598,17.598 27.598,21.918 28.5,22.82 28.5,31.75 v1(28,32.25)
  Mid 2 w0.095: v1(28,32.25) 31.29,32.25 31.668,32.628 43.412,32.628 46.347,29.693 46.347,29.161 46.606,28.903 46.963,28.903 47.22,29.16 48.34,29.16 v1(49,28.5)
  Mid 4 w0.09: v1(49,28.5) 49,27.89 52.25,24.64 52.25,14.67 52.3,14.62 52.3,11.9 51.89,11.49 51.89,7.603 53.095,6.398 53.095,5.045 53.74,4.4 v2(53.74,3.46)
  Bottom Layer w0.15: X1.202@53.675,1.362 53.717,1.405 53.717,2.687 53.875,2.845 53.875,3.298 53.74,3.433 v2(53.74,3.46)
  other v2: 53.675,0.6
SPI_1_MISO: X1.198 X11.P54 | length 68.4
  Top Layer w0.15: X11.P54@23.62,18.2 24.732,18.2 24.932,18 v1(25,18)
  Mid 3 w0.095: v1(25,18) 25,20.16 25.795,20.955 25.795,21.795 26.402,22.402 26.644,22.402 26.848,22.606 26.848,30.498 27.25,30.901 v1(27.25,31.5)
  Mid 2 w0.095: v1(27.25,31.5) 27.653,31.903 31.653,31.903 32.14,32.39 43.29,32.39 44.86,30.82 44.86,29.899 45.106,29.653 45.339,29.653 45.597,29.394 45.597,29.161 45.856,28.903 46.089,28.903 46.491,28.5 v1(47.5,28.5)
  Mid 4 w0.09: v1(47.5,28.5) 47.5,27.63 51.61,23.52 51.61,14.02 51.785,13.845 51.785,12.775 51.39,12.38 51.39,9.64 50.905,9.155 50.905,7.125 51.3,6.73 51.3,4.188 51.595,3.893 51.595,2.917 51.857,2.655 52.045,2.655 v2(52.675,2.025)
  other v2: 52.675,0.6
SPI_1_MOSI: X1.200 X11.P56 | length 70
  Top Layer w0.15: X11.P56@23.62,17.8 24.67,17.8 25.22,17.25 v1(26.5,17.25)
  Mid 3 w0.095: v1(26.5,17.25) 26.903,17.653 26.903,21.894 27.106,22.098 27.228,22.098 28,22.87 v1(28,31.5)
  Mid 2 w0.095: v1(28,31.5) 31.89,31.5 32.5,32.11 43.24,32.11 44.52,30.83 44.52,29.86 44.847,29.532 44.847,29.161 45.856,28.153 47.903,28.153 v1(48.25,28.5)
  Mid 4 w0.09: v1(48.25,28.5) 48.25,27.69 51.51,24.43 51.93,24.01 51.93,14.51 52.04,14.4 52.04,12.36 51.63,11.95 51.63,5.132 52.345,4.417 52.345,2.855 v2(53.175,2.025)
  other v2: 53.175,0.6
SPI_2_CLK: X1.52 X12.S20 | length 60.9
  Top Layer w0.15: X12.S20@48.62,22.5 48.643,22.523 49.285,22.523 49.388,22.625 49.675,22.625 50.125,23.075 50.125,23.405 49.905,23.625 49.852,23.625 49.764,23.713 v1@49.764,24.006
  Mid 3 w0.095: v1(46,5.25) 46,5.73 45.82,5.91 45.82,20.66 49.16,24 v1(49.75,24)
  Mid 2 w0.095: v1(14.5,4.5) 14.903,4.098 16.661,4.098 18.106,2.652 32.411,2.652 33.134,3.375 33.525,3.375 35.747,5.597 37.973,5.597 38.18,5.39 41.149,5.39 41.369,5.61 42.67,5.61 42.86,5.42 44.179,5.42 44.356,5.598 44.644,5.598 44.796,5.445 45.722,5.445 45.917,5.25 v1(46,5.25)
  Bottom Layer w0.15: X1.52@14.175,1.362 14.175,2.795 14.125,2.845 14.125,4.125 v1(14.5,4.5)
  other v2: 14.175,0.6
SPI_2_CS: X1.54 X12.S18 | length 57.9
  Top Layer w0.15: X12.S18@48.62,22.9 48.645,22.925 49.4,22.925 49.725,23.25 v1(49.75,23.25)
  Mid 3 w0.095: v1(46.75,5.25) 46.75,6.03 46.47,6.31 46.47,19.43 47.153,20.113 47.153,20.394 47.356,20.597 47.907,20.597 49.75,22.44 v1(49.75,23.25)
  Mid 2 w0.095: v1(15.25,4.5) 16.89,4.5 17.987,3.403 32.103,3.403 34.59,5.89 38.119,5.89 38.356,5.652 38.712,5.652 38.93,5.87 44.647,5.87 44.877,5.64 46.36,5.64 v1(46.75,5.25)
  Bottom Layer w0.15: X1.54@14.675,1.362 14.717,1.405 14.717,2.687 14.875,2.845 14.875,3.155 14.875,4.125 v1(15.25,4.5)
  other v2: 14.675,0.6
SPI_2_MISO: X1.58 X12.S24 | length 57.5
  Top Layer w0.15: X12.S24@48.62,21.7 48.645,21.725 49.115,21.725 49.215,21.825 49.295,21.825 49.595,22.125 50.125,22.125 v1(50.5,22.5)
  Mid 3 w0.095: v1(46.75,4.5) 47.098,4.848 47.098,6.122 46.78,6.44 46.78,18.521 47.92,19.661 47.92,19.92 v1(50.5,22.5)
  Mid 2 w0.095: v1(16,3.75) 17.57,2.18 34.42,2.18 34.893,2.652 34.894,2.652 35.848,3.606 35.848,3.608 37.35,5.11 39.08,5.11 39.288,4.902 45.339,4.902 45.741,4.5 v1(46.75,4.5)
  Bottom Layer w0.15: X1.58@15.675,1.362 15.675,2.795 15.625,2.845 15.625,3.375 v1(16,3.75)
  other v2: 15.675,0.6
